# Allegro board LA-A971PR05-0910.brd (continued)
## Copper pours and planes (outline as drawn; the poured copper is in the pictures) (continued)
SW_1.35V on TOP (solid shape): 198.11,13.56 198.11,12.99 198.74,12.36 201.22,12.36 201.28,12.29 201.28,10.39 200.9,10.01 196.39,10.01 195.38,11.02 194.74,11.02 194.55,11.21 194.55,12.67 194.74,12.86 195.57,12.86 195.76,13.06 195.76,13.56 195.89,13.69 197.98,13.69
SW_1.35V on BOTTOM (solid shape): 198.43,13.25 198.43,9.44 197.85,8.86 196.27,8.86 195.57,8.17 192.84,8.17 192.52,8.48 192.52,11.98 193.15,12.61 194.87,12.61 195.95,13.69 197.98,13.69
SW_1.35V on IN4 (solid shape): 197.09,11.34 197.09,10.39 196.96,10.26 195.25,10.26 195.12,10.39 195.12,11.28 195.31,11.47 196.96,11.47
SW_1.35V on IN4 (solid shape): 189.6,9.5 189.6,9.12 189.34,8.86 189.03,8.86 188.58,8.42 187.76,8.42 187.63,8.55 187.63,8.8 187.76,8.93 188.01,8.93 189.09,10.01
SW_+V1.05SP on TOP (solid shape): 190.74,63.79 190.74,60.36 190.61,60.24 189.79,60.24 189.73,60.3 189.73,62.14 189.47,62.39 188.52,62.39 188.46,62.46 188.46,64.24 190.3,64.24
SW_+V1.05SP on BOTTOM (solid shape): 193.14,63.69 193.09,63.65 192.19,63.65 191.06,62.52 191.06,61.25 189.92,61.25 189.85,61.32 189.85,62.39 189.34,62.9 189.34,65.57 189.61,65.84 193.14,65.84
UG_3V on TOP (solid shape): 203.51,51.54 203.51,51.41 202.68,50.58 201.66,50.58 201.6,50.65 201.6,50.77 201.79,50.96 202.04,50.96 202.87,51.79 203.25,51.79
UG_3V on TOP (solid shape): 206.3,58.58 206.3,57.63 205.73,57.06 205.73,55.54 205.54,55.35 205.28,55.35 205.08,55.55 205.08,57.87 205.92,58.71 206.17,58.71
UG_3V on IN1 (solid shape): 205.79,56.33 205.79,55.22 205.54,54.97 204.9,54.97 204.65,55.22 204.65,56.36 204.81,56.52 205.6,56.52
UG_3V on IN1 (solid shape): 204.33,52.3 204.33,52.11 203.06,50.84 202.62,50.84 202.43,51.03 202.43,51.22 203.31,52.11 203.31,52.49 203.57,52.74 203.89,52.74
UG_5V on TOP (solid shape): 197.16,58.58 197.16,57.89 196.96,57.7 195.89,57.7 195.69,57.89 195.69,58.65 195.89,58.84 196.9,58.84
UG_5V on TOP (solid shape): 199.25,50.84 199.57,50.84 199.63,50.77 199.63,50.65 199.57,50.58 198.62,50.58 197.85,51.35 197.85,51.73 197.98,51.85 198.23,51.85
UG_5V on IN2 (solid shape): 196.62,58.55 196.62,57.03 196.3,56.71 195.79,56.71 195.54,56.97 195.54,58.62 195.73,58.81 196.36,58.81
UG_5V on IN2 (solid shape): 198.74,51.28 198.74,50.96 198.62,50.84 197.03,50.84 196.65,51.22 196.65,51.41 197.09,51.85 198.17,51.85
N17156946 on TOP (solid shape): 82.16,85.25 82.16,83.73 81.46,83.73 81.01,83.29 81.01,82.65 80.95,82.59 80.12,82.59 79.87,82.84 79.87,85.51 79.68,85.7 79.68,86.21 79.81,86.33 81.08,86.33
N17156948 on TOP (solid shape): 83.97,88.06 83.97,86.91 83.79,86.72 82.27,86.72 82.1,86.9 82.1,88.13 82.25,88.28 83.75,88.28
N20363967 on TOP (solid shape): 256.58,38.51 256.58,38.2 257.42,37.36 258.31,37.36 258.36,37.31 258.36,37.21 258.31,37.16 257.21,37.16 255.08,39.29 254.2,39.29 254.11,39.38 254.11,40.23 254.17,40.29 254.79,40.29
N20813052 on BOTTOM (solid shape): 95.3,14.33 95.3,12.45 95.64,12.1 96.51,12.1 96.7,11.91 96.7,9.94 96.44,9.69 93.65,9.69 93.27,10.07 93.27,13.12 94.6,14.45 95.17,14.45
N24368370 on TOP (solid shape): 194.38,72.64 194.38,71.92 194.32,71.86 192.78,71.86 192.7,71.94 192.7,72.6 192.81,72.71 194.31,72.71

Small or netless copper shapes (teardrops, artwork), in the pictures only: 53 on TOP, 324 on BOTTOM, 1 on IN1, 1 on IN2, 2 on IN4

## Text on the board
Ref Des/Silkscreen Bottom: COPYRIGHT 2014 | ALL RIGHT RESERVED | REV:X02 | PWB 89XM3 | DDR3L | DIMM A | LOW VOLTAGE | DIMM B | mSATA
User.Comments: ZBZ00 | LAA971P | 2014-09-10 | 2015-09-10 | Monika | 0.5 | (X02)
Ref Des/Silkscreen Top: ST3 | M2X3 | ST2 | 4 | 3 | 2 | 7 | 6 | 1 | 5
User.35: FIGURE | SIZE | 8.0 | 10.0 | 20.0 | 28.0 | 35.0 | 39.0 | 47.0 | 83.0 | 91.0 | 98.0 | 110.0 | 130.0 | 134.0 | 40.0 | 43.0 | 63.0 | 71.0 | 118.0 | 39.0x28.0 | 39.0x33.0 | 55.0x24.0 | 67.0x31.0 | 69.0x28.0 | 71.0x31.0 | 79.0x31.0 | 87.0x31.0 | 94.0x28.0 | 102.0x28.0 | 102.0x31.0 | 110.0x39.0 | 118.0x30.0 | 55.0x43.0 | DRILL CHART: TOP to BOTTOM | ALL UNITS ARE IN MILS | TOLERANCE | +3.0/-3.0 | +2.0/-2.0 | PLATED | NON-PLATED | QTY | 5178 | 18 | 29 | 27 | 10 | 9 | 1 | 3 | 2 | 4 | 6 | 5 | 7
User.36: trace Width | Single 52ohm | Width/space | Single 50ohm | Single 48ohm | no ref | 5.2mil | 3.3mil | 4.8mil | 4mil | 4.5 / 3.2 | 4 / 4.5 | 3.6 / 3.2 | 3.3 / 3.5 | 4 / 6.5 | 3.3 / 11.7 | 3.5 / 9 | 4 / 6 | 9.5 / 5 | 11 / 5 | Ref | SB_1_0mm (0_5oz)-10L(4mil  5mil 50ohm)-stack-up-130808 | L1-TOP | L2-GND1 | L3-IN1 | L4-GND2 | L4-IN2 | L5-IN3 | L7-VCC | L8-IN4 | L9-GND3 | L10-BOT | LAYER | NAME | STACKUP: 10 LAYER | 39 ohm | 50 ohm | THICKNESS=1.0mm | 85 ohm | 90 ohm | 100 ohm
